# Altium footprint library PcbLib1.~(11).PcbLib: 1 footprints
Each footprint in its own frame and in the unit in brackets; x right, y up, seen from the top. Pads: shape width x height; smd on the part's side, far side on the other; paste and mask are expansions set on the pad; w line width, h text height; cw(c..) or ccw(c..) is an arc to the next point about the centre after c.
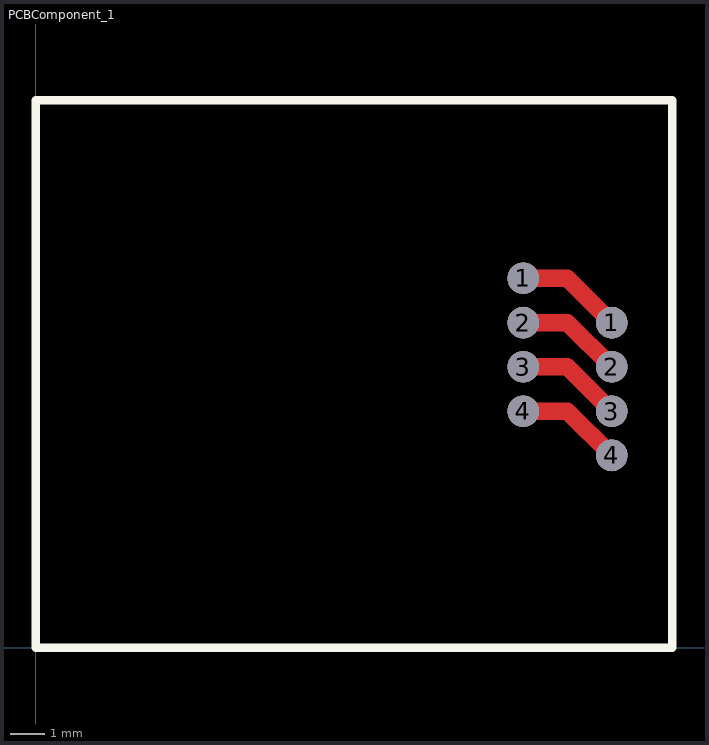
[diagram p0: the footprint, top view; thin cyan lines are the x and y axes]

## PCBComponent_1 [mm]
pads (8):
  round 0.91 hole 0.9: 1(13.975,10.595) 1(16.515,9.325) 2(13.975,9.325) 2(16.515,8.055) 3(13.975,8.055) 3(16.515,6.785) 4(13.975,6.785) 4(16.515,5.515)
Top Layer:
  lines w0.5: 13.975,6.785 15.245,6.785 16.515,5.515 ; 13.975,8.055 15.245,8.055 16.515,6.785 ; 13.975,9.325 15.245,9.325 16.515,8.055 ; 13.975,10.595 15.245,10.595 16.515,9.325
Top Overlay:
  lines w0.254: 0,0 18.25,0 18.25,15.7 0,15.7 0,0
